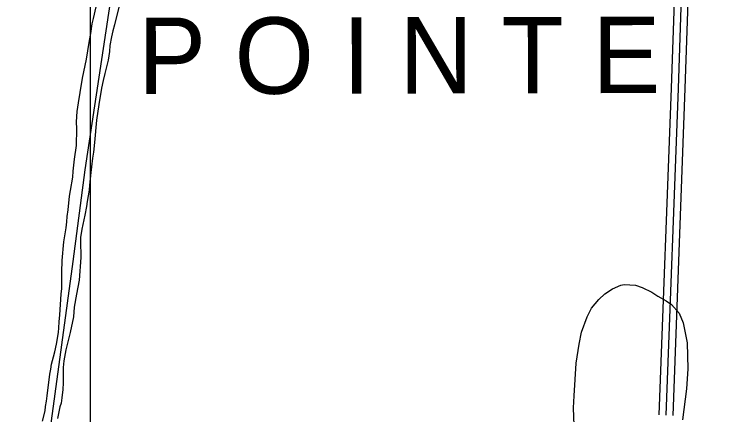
# Model space of a CAD drawing. Extents: x 3245246 to 3283090, y 806824 to 832173.
# Drawn here: x 3259722 to 3261266, y 815617 to 816493 of the extents above; entities that cross this region are included whole.
import ezdxf

# ---------------------------------------------------------------- set-up
doc = ezdxf.new("R2010")
doc.units = 0
for name, color, linetype in [('V-GRID-MAJR', 7, 'Continuous'), ('V-ROAD-CNTR', 7, 'Continuous'), ('V-SITE-VEGE', 7, 'Continuous'), ('V-TOPO-GNAM-IDEN', 7, 'Continuous'), ('V-TOPO-SHOR', 7, 'Continuous')]:
    doc.layers.add(name, color=color, linetype=linetype)

msp = doc.modelspace()

# ---------------------------------------------------------------- linework, layer by layer
at = {"layer": 'V-GRID-MAJR'}
msp.add_spline([(3259886.4, 812208.7), (3259889.9, 818267.9), (3259893.4, 824330.1), (3259897, 830392.4), (3259897, 830395.5)], degree=3, dxfattribs=at)
at = {"layer": 'V-ROAD-CNTR'}
for points in [[(3261255.6, 818407.4), (3261265, 818362), (3261266.1, 818313.9), (3261258.8, 818159.7), (3261250.3, 817948.9), (3261239.9, 817746.5), (3261232.1, 817487.4), (3261217.9, 817147.2), (3261201.1, 816730.8), (3261187.6, 816330.3), (3261160.8, 815616)], [(3261226.2, 818401.3), (3261235.1, 818358.6), (3261236.1, 818314.2), (3261228.8, 818161), (3261220.4, 817950.3), (3261210, 817747.7), (3261202.1, 817488.5), (3261187.9, 817148.5), (3261171.1, 816731.9), (3261157.6, 816331.3), (3261130.8, 815617.1)], [(3261240.9, 818404.3), (3261250, 818360.3), (3261251.1, 818314), (3261243.8, 818160.3), (3261235.4, 817949.6), (3261225, 817747.1), (3261217.1, 817487.9), (3261202.9, 817147.9), (3261186.1, 816731.3), (3261172.6, 816330.8), (3261145.8, 815616.5)]]:
    msp.add_lwpolyline(points, dxfattribs=at)
at = {"layer": 'V-SITE-VEGE'}
for p, q in [((3259954.6, 816522.3), (3259944.6, 816484.7)), ((3259895.1, 816483.4), (3259901.1, 816508.7)), ((3259892.7, 816472.1), (3259895.1, 816483.4)), ((3259944.6, 816484.7), (3259941.3, 816469.8)), ((3259889.4, 816450.8), (3259892.7, 816472.1)), ((3259941.3, 816469.8), (3259937.3, 816456.5)), ((3259886.4, 816435.2), (3259889.4, 816450.8)), ((3259934.3, 816443.5), (3259930.9, 816424.6)), ((3259937.3, 816456.5), (3259934.3, 816443.5)), ((3259883.1, 816412.6), (3259886.4, 816435.2)), ((3259880.1, 816394.3), (3259883.1, 816412.6)), ((3259930.9, 816424.6), (3259929.9, 816411.6)), ((3259929.9, 816411.6), (3259927.3, 816392.7)), ((3259877.4, 816380.7), (3259880.1, 816394.3)), ((3259927.3, 816392.7), (3259920.3, 816363.4)), ((3259871.4, 816353.1), (3259877.4, 816380.7)), ((3259866.1, 816321.9), (3259871.4, 816353.1)), ((3259920.3, 816363.4), (3259916.3, 816347.8)), ((3259916.3, 816347.8), (3259912.6, 816330.9)), ((3259862.8, 816299), (3259866.1, 816321.9)), ((3259912.6, 816330.9), (3259907.3, 816295.6)), ((3259859.8, 816280), (3259862.8, 816299)), ((3259907.3, 816295.6), (3259901.7, 816261.4)), ((3259858.1, 816257.8), (3259859.8, 816280)), ((3259901.7, 816261.4), (3259897.6, 816212.6)), ((3259858.8, 816242.5), (3259858.1, 816257.8)), ((3259858.4, 816205.6), (3259858.8, 816242.5)), ((3259897.6, 816212.6), (3259895.3, 816191.3)), ((3259853.8, 816176.3), (3259858.4, 816205.6)), ((3259895.3, 816191.3), (3259893, 816178)), ((3259851.1, 816149.8), (3259853.8, 816176.3)), ((3259893, 816178), (3259891, 816159)), ((3259891, 816159), (3259889.3, 816147.1)), ((3259845.1, 816107.5), (3259850.1, 816136.8)), ((3259850.1, 816136.8), (3259851.1, 816149.8)), ((3259889.3, 816147.1), (3259886.3, 816119.2)), ((3259886.3, 816119.2), (3259885.7, 816108.5)), ((3259842.8, 816094.9), (3259845.1, 816107.5)), ((3259885.7, 816108.5), (3259881.3, 816083.6)), ((3259840.1, 816065), (3259842.8, 816094.9)), ((3259879.7, 816072.6), (3259876, 816053.7)), ((3259881.3, 816083.6), (3259879.7, 816072.6)), ((3259838.1, 816050.4), (3259840.1, 816065)), ((3259837.1, 816038.8), (3259838.1, 816050.4)), ((3259876, 816053.7), (3259869.7, 816023.1)), ((3259835.5, 816025.8), (3259837.1, 816038.8)), ((3259830.5, 815995.6), (3259835.5, 816025.8)), ((3259868.7, 816013.5), (3259866.7, 816005.5)), ((3259869.7, 816023.1), (3259868.7, 816013.5)), ((3259827.1, 815954.3), (3259830.5, 815995.6)), ((3259866.7, 816005.5), (3259867, 815997.2)), ((3259867, 815997.2), (3259867.7, 815961.3)), ((3259826.4, 815928.8), (3259827.1, 815954.3)), ((3259867.7, 815961.3), (3259864, 815911.5)), ((3259825.8, 815913.8), (3259826.4, 815928.8)), ((3259825.8, 815893.2), (3259825.8, 815913.8)), ((3259864, 815911.5), (3259858, 815881.2)), ((3259824.8, 815880.9), (3259825.8, 815893.2)), ((3261012.9, 815881.3), (3261029.4, 815892.6)), ((3261029.4, 815892.6), (3261047.7, 815900.4)), ((3261047.7, 815900.4), (3261054.7, 815902.2)), ((3261054.7, 815902.2), (3261079.9, 815900.4)), ((3261079.9, 815900.4), (3261093.8, 815895.2)), ((3261093.8, 815895.2), (3261115.6, 815885.6)), ((3259821.8, 815836), (3259824.8, 815880.9)), ((3259858, 815881.2), (3259853.3, 815852.3)), ((3260999.8, 815869.1), (3261012.9, 815881.3)), ((3261115.6, 815885.6), (3261128.6, 815876.9)), ((3261128.6, 815876.9), (3261146.9, 815866.5)), ((3260983.3, 815850), (3260999.8, 815869.1)), ((3261146.9, 815866.5), (3261158.2, 815858.6)), ((3261158.2, 815858.6), (3261174.7, 815839.5)), ((3259853.3, 815852.3), (3259851.3, 815831.4)), ((3260973.7, 815831.7), (3260983.3, 815850)), ((3259820.4, 815820.8), (3259821.8, 815836)), ((3259851.3, 815831.4), (3259844, 815797.5)), ((3260961.5, 815797.8), (3260973.7, 815831.7)), ((3261174.7, 815839.5), (3261183.4, 815818.6)), ((3259819.8, 815807.5), (3259820.4, 815820.8)), ((3261183.4, 815818.6), (3261192.1, 815774.2)), ((3259814.4, 815771.9), (3259818.8, 815797.5)), ((3259818.8, 815797.5), (3259819.8, 815807.5)), ((3259844, 815797.5), (3259834.7, 815758.9)), ((3260956.3, 815771.7), (3260961.5, 815797.8)), ((3259810.8, 815755), (3259814.4, 815771.9)), ((3260950.2, 815729.9), (3260956.3, 815771.7)), ((3261192.1, 815774.2), (3261193.8, 815717.7)), ((3259807.8, 815744.3), (3259810.8, 815755)), ((3259834.7, 815758.9), (3259830.7, 815735)), ((3259803.8, 815728), (3259807.8, 815744.3)), ((3259830.7, 815735), (3259829, 815720.4)), ((3259801.8, 815716.7), (3259803.8, 815728)), ((3259829, 815720.4), (3259829, 815687.2)), ((3260945.8, 815658.6), (3260950.2, 815729.9)), ((3261193.8, 815717.7), (3261191.2, 815674.2)), ((3259793.8, 815658.6), (3259800.1, 815706.1)), ((3259800.1, 815706.1), (3259801.8, 815716.7)), ((3259829, 815687.2), (3259828.4, 815672.5)), ((3259828.4, 815672.5), (3259826.4, 815654.6)), ((3261191.2, 815674.2), (3261182.4, 815606.3)), ((3259792.5, 815647.3), (3259793.8, 815658.6)), ((3260944.1, 815632.5), (3260945.8, 815658.6)), ((3259790.1, 815635.3), (3259792.5, 815647.3)), ((3259824.4, 815642.6), (3259821.7, 815634.7)), ((3259826.4, 815654.6), (3259824.4, 815642.6)), ((3259784.1, 815603.1), (3259789.5, 815626)), ((3259789.5, 815626), (3259790.1, 815635.3)), ((3259821.7, 815634.7), (3259816.4, 815609.1)), ((3260945.8, 815594.2), (3260944.1, 815632.5))]:
    msp.add_line(p, q, dxfattribs=at)
at = {"layer": 'V-TOPO-SHOR'}
msp.add_lwpolyline([(3260059.9, 817368.6), (3259876, 816152.9), (3259850.3, 815952.4), (3259721.9, 815009.6)], dxfattribs=at)

# ---------------------------------------------------------------- texts
at = {"layer": 'V-TOPO-GNAM-IDEN'}
msp.add_text('P O I N T E', height=167, rotation=0.1065, dxfattribs=at).set_placement((3259992.6, 816318.4))

doc.saveas('drawing.dxf')
